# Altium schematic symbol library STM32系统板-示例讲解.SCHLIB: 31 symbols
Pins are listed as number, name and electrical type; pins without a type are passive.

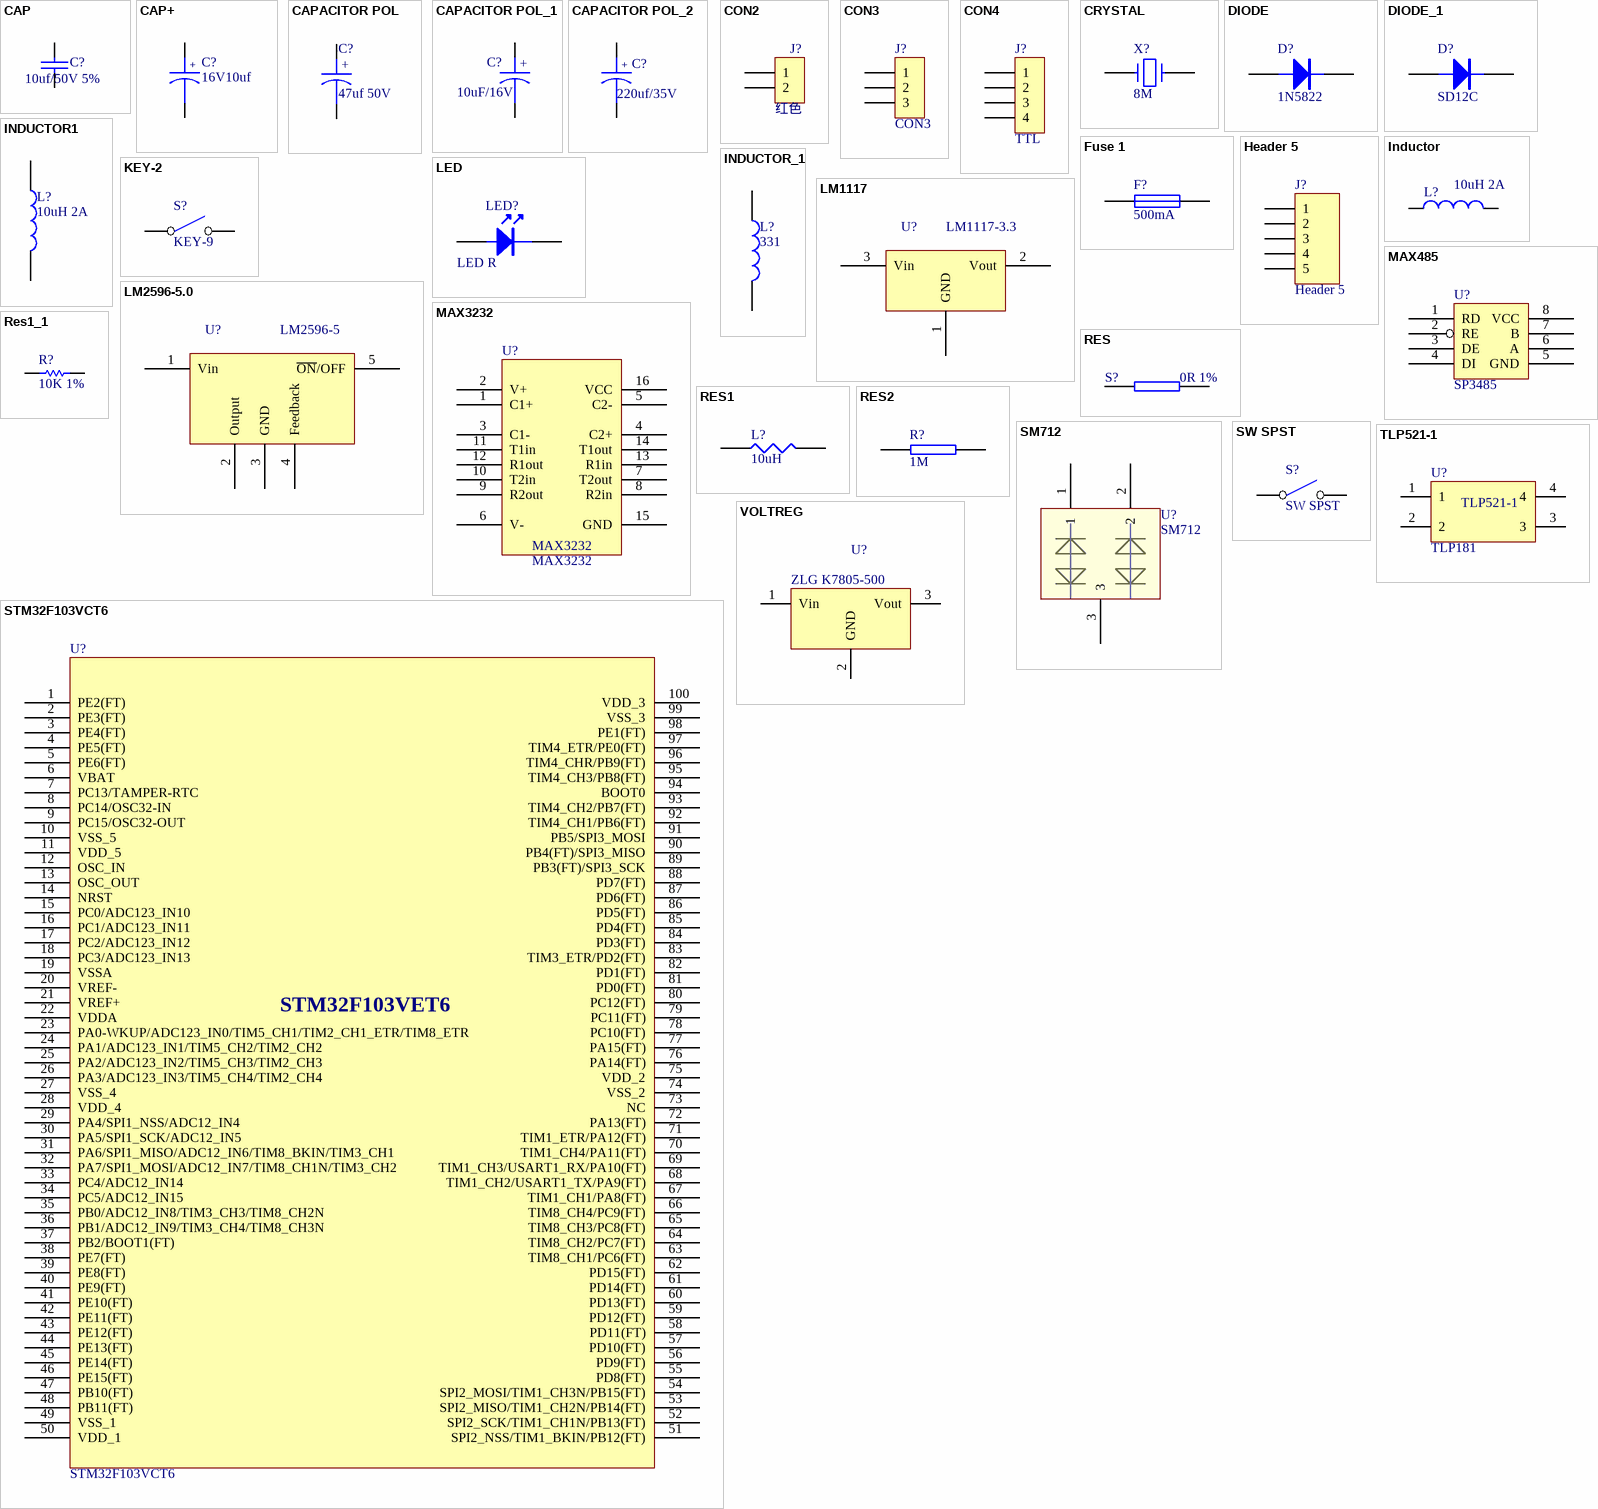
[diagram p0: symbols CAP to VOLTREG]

## CAP
designator C?, comment 10uf/50V 5%
Capacitor
footprint 0805C
pins: 1, 2

## CAP+
designator C?, comment 16V10uf
footprint 1206-2
pins: 1, 2

## CAPACITOR POL
designator C?, comment 47uf 50V
Capacitor
footprint C6.5-35V47uf
pins: 1, 2

## CAPACITOR POL_1
designator C?, comment 10uF/16V
Capacitor
footprint 0805C
pins: 1, 2

## CAPACITOR POL_2
designator C?, comment 220uf/35V
Capacitor
footprint C10-35V330uf
pins: 1, 2

## CON2
designator J?, comment 红色
Connector
footprint CON-2P-3.81
pins: 1, 2

## CON3
designator J?
Connector
footprint CON-3P-3.81
pins: 1, 2, 3

## CON4
designator J?, comment TTL
Connector
footprint SIP4
pins: 1, 2, 3, 4

## CRYSTAL
designator X?, comment 8M
footprint CRYSTAL-T
pins: 1, 2

## DIODE
designator D?, comment 1N5822
Diode
footprint SS34
pins: 1 A, 2 K

## DIODE_1
designator D?, comment SD12C
Diode
footprint SD12C
pins: 1 A, 2 K

## Fuse 1
designator F?, comment 500mA
Fuse
footprint 1812
pins: 1, 2

## Header 5
designator J?
Header, 5-Pin
footprint CON-5P-3.81
signal-integrity model Connector
pins: 1, 2, 3, 4, 5

## Inductor
designator L?  value 10uH 2A  (hidden comment: Inductor)
Code_IEC: 1005
footprint LC-8.2
pins: 1, 2

## INDUCTOR1
designator L?, comment 10uH 2A
footprint LC-8.2
pins: 1, 2

## INDUCTOR_1
designator L?, comment 331
footprint LC-10
pins: 1, 2

## KEY-2
designator S?, comment KEY-9
footprint SIP2
pins: 1 COMMON, 2 NO

## LED
designator LED?, comment LED R
footprint 0805D
pins: 1, 2

## LM1117
designator U?, comment LM1117-3.3
footprint SOT-223
pins: 1 GND, 2 Vout, 3 Vin

## LM2596-5.0
designator U?, comment LM2596-5
footprint TO-263-5
pins: 1 Vin, 2 Output, 3 GND, 4 Feedback, 5 ~{ON}/OFF

## MAX485
designator U?, comment SP3485
footprint SO-8
pins: 1 RD, 2 RE, 3 DE, 4 DI, 5 GND, 6 A, 7 B, 8 VCC

## MAX3232
designator U?
footprint SO-16
pins: 1 C1+, 2 V+, 3 C1-, 4 C2+, 5 C2-, 6 V-, 7 T2out, 8 R2in, 9 R2out, 10 T2in, 11 T1in, 12 R1out, 13 R1in, 14 T1out, 15 GND, 16 VCC

## RES
designator S?, comment 0R 1%
footprint 0805R
pins: 1, 2

## RES1
designator L?, comment 10uH
footprint 0805
pins: 1, 2

## Res1_1
designator R?, comment 10K 1%
Resistor
footprint 0805R
simulation model RESISTOR (Resistor)
signal-integrity model Res
pins: 1, 2

## RES2
designator R?, comment 1M
footprint 0805R
pins: 1, 2

## SM712
designator U?
footprint SM712
pins: 1, 2, 3

## STM32F103VCT6
designator U?
footprint LQFP100
pins: 1 PE2(FT), 2 PE3(FT), 3 PE4(FT), 4 PE5(FT), 5 PE6(FT), 6 VBAT, 7 PC13/TAMPER-RTC, 8 PC14/OSC32-IN, 9 PC15/OSC32-OUT, 10 VSS_5, 11 VDD_5, 12 OSC_IN, 13 OSC_OUT, 14 NRST, 15 PC0/ADC123_IN10, 16 PC1/ADC123_IN11, 17 PC2/ADC123_IN12, 18 PC3/ADC123_IN13, 19 VSSA, 20 VREF-, 21 VREF+, 22 VDDA, 23 PA0-WKUP/ADC123_IN0/TIM5_CH1/TIM2_CH1_ETR/TIM8_ETR, 24 PA1/ADC123_IN1/TIM5_CH2/TIM2_CH2, 25 PA2/ADC123_IN2/TIM5_CH3/TIM2_CH3, 26 PA3/ADC123_IN3/TIM5_CH4/TIM2_CH4, 27 VSS_4, 28 VDD_4, 29 PA4/SPI1_NSS/ADC12_IN4, 30 PA5/SPI1_SCK/ADC12_IN5, 31 PA6/SPI1_MISO/ADC12_IN6/TIM8_BKIN/TIM3_CH1, 32 PA7/SPI1_MOSI/ADC12_IN7/TIM8_CH1N/TIM3_CH2, 33 PC4/ADC12_IN14, 34 PC5/ADC12_IN15, 35 PB0/ADC12_IN8/TIM3_CH3/TIM8_CH2N, 36 PB1/ADC12_IN9/TIM3_CH4/TIM8_CH3N, 37 PB2/BOOT1(FT), 38 PE7(FT), 39 PE8(FT), 40 PE9(FT), 41 PE10(FT), 42 PE11(FT), 43 PE12(FT), 44 PE13(FT), 45 PE14(FT), 46 PE15(FT), 47 PB10(FT), 48 PB11(FT), 49 VSS_1, 50 VDD_1, 51 SPI2_NSS/TIM1_BKIN/PB12(FT), 52 SPI2_SCK/TIM1_CH1N/PB13(FT), 53 SPI2_MISO/TIM1_CH2N/PB14(FT), 54 SPI2_MOSI/TIM1_CH3N/PB15(FT), 55 PD8(FT), 56 PD9(FT), 57 PD10(FT), 58 PD11(FT), 59 PD12(FT), 60 PD13(FT), 61 PD14(FT), 62 PD15(FT), 63 TIM8_CH1/PC6(FT), 64 TIM8_CH2/PC7(FT), 65 TIM8_CH3/PC8(FT), 66 TIM8_CH4/PC9(FT), 67 TIM1_CH1/PA8(FT), 68 TIM1_CH2/USART1_TX/PA9(FT), 69 TIM1_CH3/USART1_RX/PA10(FT), 70 TIM1_CH4/PA11(FT), 71 TIM1_ETR/PA12(FT), 72 PA13(FT), 73 NC, 74 VSS_2, 75 VDD_2, 76 PA14(FT), 77 PA15(FT), 78 PC10(FT), 79 PC11(FT), 80 PC12(FT), 81 PD0(FT), 82 PD1(FT), 83 TIM3_ETR/PD2(FT), 84 PD3(FT), 85 PD4(FT), 86 PD5(FT), 87 PD6(FT), 88 PD7(FT), 89 PB3(FT)/SPI3_SCK, 90 PB4(FT)/SPI3_MISO, 91 PB5/SPI3_MOSI, 92 TIM4_CH1/PB6(FT), 93 TIM4_CH2/PB7(FT), 94 BOOT0, 95 TIM4_CH3/PB8(FT), 96 TIM4_CHR/PB9(FT), 97 TIM4_ETR/PE0(FT), 98 PE1(FT), 99 VSS_3, 100 VDD_3

## SW SPST
designator S?
footprint SIP2
pins: 1 COMMON, 2 NO

## TLP521-1
designator U?, comment TLP181
footprint Model Name (Footprint not found)
footprint Model Name (Footprint not found)
footprint TLP-181
pins: 1 (power), 2 (power), 3 (power), 4 (power)

## VOLTREG
designator U?, comment ZLG K7805-500
footprint TO220H
footprint TO-220
pins: 1 Vin, 2 GND, 3 Vout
